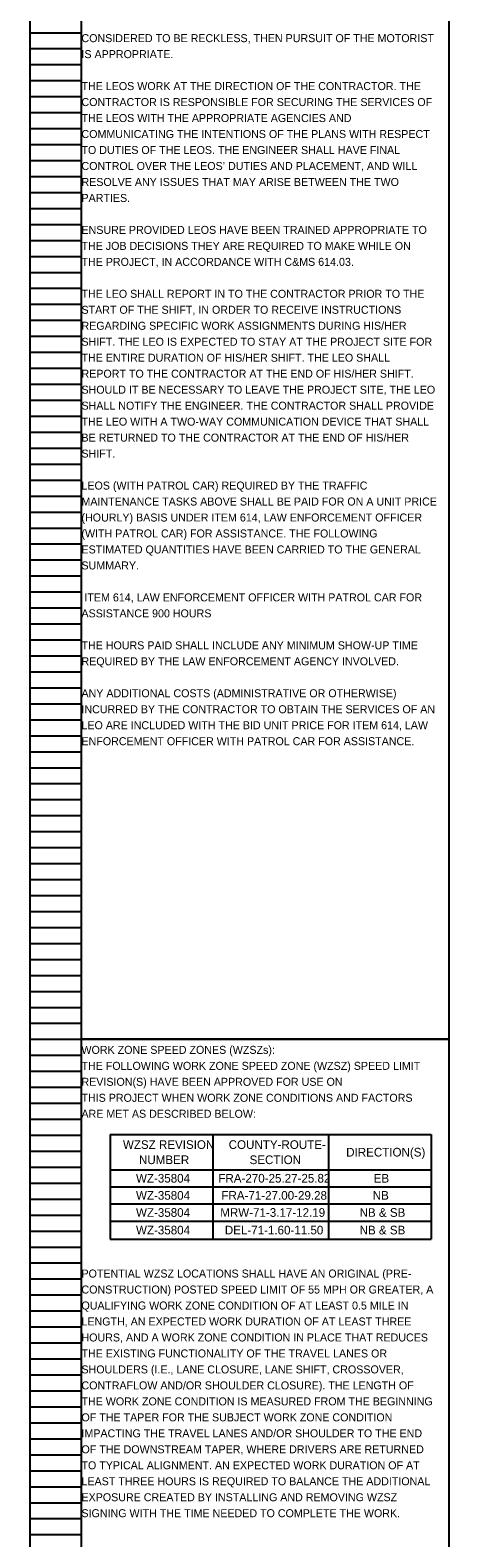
# Model space of a CAD drawing. Extents: x 16463 to 16500, y 5400 to 5823.
# Drawn here: x 16463.05 to 16470.39, y 5532.5 to 5558.92 of the extents above; entities that cross this region are included whole.
import ezdxf

# ---------------------------------------------------------------- set-up
doc = ezdxf.new("R2010")
doc.units = 0
for name, color, linetype in [('Default', 7, 'Continuous'), ('SC_Scratch1', 7, 'Continuous'), ('SH_Data', 7, 'Continuous'), ('SH_Text', 7, 'Continuous')]:
    doc.layers.add(name, color=color, linetype=linetype)

msp = doc.modelspace()

# ---------------------------------------------------------------- linework, layer by layer
at = {"layer": 'Default'}
for p, q in [((16464.454, 5539.562), (16470.079, 5539.562)), ((16464.454, 5539.562), (16464.454, 5537.732)), ((16466.254, 5539.562), (16466.254, 5537.732)), ((16468.279, 5539.562), (16468.279, 5537.732)), ((16470.079, 5539.562), (16470.079, 5537.732)), ((16464.454, 5538.947), (16470.079, 5538.947)), ((16464.454, 5538.647), (16470.079, 5538.647)), ((16464.454, 5538.347), (16470.079, 5538.347)), ((16464.454, 5538.047), (16470.079, 5538.047)), ((16464.454, 5537.732), (16470.079, 5537.732))]:
    msp.add_line(p, q, dxfattribs=at)
at = {"layer": 'SC_Scratch1'}
for points in [[(16463.949, 5561.392), (16470.389, 5561.392), (16470.389, 5541.232), (16463.949, 5541.232)], [(16463.949, 5541.232), (16470.389, 5541.232), (16470.389, 5521.072), (16463.949, 5521.072)]]:
    msp.add_lwpolyline(points, close=True, dxfattribs=at)
at = {"layer": 'SH_Data'}
for p, q in [((16463.049, 5541.232), (16463.049, 5561.392)), ((16463.949, 5541.232), (16463.949, 5561.392)), ((16463.049, 5558.872), (16463.949, 5558.872)), ((16463.049, 5558.592), (16463.949, 5558.592)), ((16463.049, 5558.312), (16463.949, 5558.312)), ((16463.049, 5558.032), (16463.949, 5558.032)), ((16463.049, 5557.752), (16463.949, 5557.752)), ((16463.049, 5557.472), (16463.949, 5557.472)), ((16463.049, 5557.192), (16463.949, 5557.192)), ((16463.049, 5556.912), (16463.949, 5556.912)), ((16463.049, 5556.632), (16463.949, 5556.632)), ((16463.049, 5556.352), (16463.949, 5556.352)), ((16463.049, 5556.072), (16463.949, 5556.072)), ((16463.049, 5555.792), (16463.949, 5555.792)), ((16463.049, 5555.512), (16463.949, 5555.512)), ((16463.049, 5555.232), (16463.949, 5555.232)), ((16463.049, 5554.952), (16463.949, 5554.952)), ((16463.049, 5554.672), (16463.949, 5554.672)), ((16463.049, 5554.392), (16463.949, 5554.392)), ((16463.049, 5554.112), (16463.949, 5554.112)), ((16463.049, 5553.832), (16463.949, 5553.832)), ((16463.049, 5553.552), (16463.949, 5553.552)), ((16463.049, 5553.272), (16463.949, 5553.272)), ((16463.049, 5552.992), (16463.949, 5552.992)), ((16463.049, 5552.712), (16463.949, 5552.712)), ((16463.049, 5552.432), (16463.949, 5552.432)), ((16463.049, 5552.152), (16463.949, 5552.152)), ((16463.049, 5551.872), (16463.949, 5551.872)), ((16463.049, 5551.592), (16463.949, 5551.592)), ((16463.049, 5551.312), (16463.949, 5551.312)), ((16463.049, 5551.032), (16463.949, 5551.032)), ((16463.049, 5550.752), (16463.949, 5550.752)), ((16463.049, 5550.472), (16463.949, 5550.472)), ((16463.049, 5550.192), (16463.949, 5550.192)), ((16463.049, 5549.912), (16463.949, 5549.912)), ((16463.049, 5549.632), (16463.949, 5549.632)), ((16463.049, 5549.352), (16463.949, 5549.352)), ((16463.049, 5549.072), (16463.949, 5549.072)), ((16463.049, 5548.792), (16463.949, 5548.792)), ((16463.049, 5548.512), (16463.949, 5548.512)), ((16463.049, 5548.232), (16463.949, 5548.232)), ((16463.049, 5547.952), (16463.949, 5547.952)), ((16463.049, 5547.672), (16463.949, 5547.672)), ((16463.049, 5547.392), (16463.949, 5547.392)), ((16463.049, 5547.112), (16463.949, 5547.112)), ((16463.049, 5546.832), (16463.949, 5546.832)), ((16463.049, 5546.552), (16463.949, 5546.552)), ((16463.049, 5546.272), (16463.949, 5546.272)), ((16463.049, 5545.992), (16463.949, 5545.992)), ((16463.049, 5545.712), (16463.949, 5545.712)), ((16463.049, 5545.432), (16463.949, 5545.432)), ((16463.049, 5545.152), (16463.949, 5545.152)), ((16463.049, 5544.872), (16463.949, 5544.872)), ((16463.049, 5544.592), (16463.949, 5544.592)), ((16463.049, 5544.312), (16463.949, 5544.312)), ((16463.049, 5544.032), (16463.949, 5544.032)), ((16463.049, 5543.752), (16463.949, 5543.752)), ((16463.049, 5543.472), (16463.949, 5543.472)), ((16463.049, 5543.192), (16463.949, 5543.192)), ((16463.049, 5542.912), (16463.949, 5542.912)), ((16463.049, 5542.632), (16463.949, 5542.632)), ((16463.049, 5542.352), (16463.949, 5542.352)), ((16463.049, 5542.072), (16463.949, 5542.072)), ((16463.049, 5541.792), (16463.949, 5541.792)), ((16463.049, 5541.512), (16463.949, 5541.512)), ((16463.049, 5521.072), (16463.049, 5541.232)), ((16463.049, 5541.232), (16463.949, 5541.232)), ((16463.049, 5541.232), (16463.949, 5541.232)), ((16463.949, 5521.072), (16463.949, 5541.232)), ((16463.049, 5540.952), (16463.949, 5540.952)), ((16463.049, 5540.672), (16463.949, 5540.672)), ((16463.049, 5540.392), (16463.949, 5540.392)), ((16463.049, 5540.112), (16463.949, 5540.112)), ((16463.049, 5539.832), (16463.949, 5539.832)), ((16463.049, 5539.552), (16463.949, 5539.552)), ((16463.049, 5539.272), (16463.949, 5539.272)), ((16463.049, 5538.992), (16463.949, 5538.992)), ((16463.049, 5538.712), (16463.949, 5538.712)), ((16463.049, 5538.432), (16463.949, 5538.432)), ((16463.049, 5538.152), (16463.949, 5538.152)), ((16463.049, 5537.872), (16463.949, 5537.872)), ((16463.049, 5537.592), (16463.949, 5537.592)), ((16463.049, 5537.312), (16463.949, 5537.312)), ((16463.049, 5537.032), (16463.949, 5537.032)), ((16463.049, 5536.752), (16463.949, 5536.752)), ((16463.049, 5536.472), (16463.949, 5536.472)), ((16463.049, 5536.192), (16463.949, 5536.192)), ((16463.049, 5535.912), (16463.949, 5535.912)), ((16463.049, 5535.632), (16463.949, 5535.632)), ((16463.049, 5535.352), (16463.949, 5535.352)), ((16463.049, 5535.072), (16463.949, 5535.072)), ((16463.049, 5534.792), (16463.949, 5534.792)), ((16463.049, 5534.512), (16463.949, 5534.512)), ((16463.049, 5534.232), (16463.949, 5534.232)), ((16463.049, 5533.952), (16463.949, 5533.952)), ((16463.049, 5533.672), (16463.949, 5533.672)), ((16463.049, 5533.392), (16463.949, 5533.392)), ((16463.049, 5533.112), (16463.949, 5533.112)), ((16463.049, 5532.832), (16463.949, 5532.832)), ((16463.049, 5532.552), (16463.949, 5532.552))]:
    msp.add_line(p, q, dxfattribs=at)

# ---------------------------------------------------------------- texts
at = {"layer": 'Default'}
for s, p in [('WZSZ REVISION ', (16464.676, 5539.311)), ('COUNTY-ROUTE-', (16466.53, 5539.311)), ('NUMBER', (16464.958, 5539.045)), ('SECTION', (16466.896, 5539.045)), ('DIRECTION(S)', (16468.59, 5539.178)), ('WZ-35804', (16464.905, 5538.721)), ('FRA-270-25.27-25.82', (16466.349, 5538.721)), ('EB', (16469.072, 5538.721)), ('WZ-35804', (16464.905, 5538.421)), ('FRA-71-27.00-29.28', (16466.402, 5538.421)), ('NB', (16469.055, 5538.421)), ('WZ-35804', (16464.905, 5538.121)), ('MRW-71-3.17-12.19', (16466.382, 5538.121)), ('NB & SB', (16468.825, 5538.121)), ('WZ-35804', (16464.905, 5537.813)), ('DEL-71-1.60-11.50', (16466.462, 5537.813)), ('NB & SB', (16468.825, 5537.813))]:
    msp.add_text(s, height=0.1518, dxfattribs=at).set_placement(p)
at = {"layer": 'SH_Text'}
for s, p in [('CONSIDERED TO BE RECKLESS, THEN PURSUIT OF THE MOTORIST ', (16463.949, 5558.706)), ('IS APPROPRIATE. ', (16463.949, 5558.426)), ('THE LEOS WORK AT THE DIRECTION OF THE CONTRACTOR. THE ', (16463.949, 5557.866)), ('CONTRACTOR IS RESPONSIBLE FOR SECURING THE SERVICES OF ', (16463.949, 5557.586)), ('THE LEOS WITH THE APPROPRIATE AGENCIES AND ', (16463.949, 5557.306)), ('COMMUNICATING THE INTENTIONS OF THE PLANS WITH RESPECT ', (16463.949, 5557.026)), ('TO DUTIES OF THE LEOS. THE ENGINEER SHALL HAVE FINAL ', (16463.949, 5556.746)), ('CONTROL OVER THE LEOS’ DUTIES AND PLACEMENT, AND WILL ', (16463.949, 5556.466)), ('RESOLVE ANY ISSUES THAT MAY ARISE BETWEEN THE TWO ', (16463.949, 5556.186)), ('PARTIES. ', (16463.949, 5555.906)), ('ENSURE PROVIDED LEOS HAVE BEEN TRAINED APPROPRIATE TO ', (16463.949, 5555.346)), ('THE JOB DECISIONS THEY ARE REQUIRED TO MAKE WHILE ON ', (16463.949, 5555.066)), ('THE PROJECT, IN ACCORDANCE WITH C&MS 614.03. ', (16463.949, 5554.786)), ('THE LEO SHALL REPORT IN TO THE CONTRACTOR PRIOR TO THE ', (16463.949, 5554.226)), ('START OF THE SHIFT, IN ORDER TO RECEIVE INSTRUCTIONS ', (16463.949, 5553.946)), ('REGARDING SPECIFIC WORK ASSIGNMENTS DURING HIS/HER ', (16463.949, 5553.666)), ('SHIFT. THE LEO IS EXPECTED TO STAY AT THE PROJECT SITE FOR ', (16463.949, 5553.386)), ('THE ENTIRE DURATION OF HIS/HER SHIFT. THE LEO SHALL ', (16463.949, 5553.106)), ('REPORT TO THE CONTRACTOR AT THE END OF HIS/HER SHIFT. ', (16463.949, 5552.826)), ('SHOULD IT BE NECESSARY TO LEAVE THE PROJECT SITE, THE LEO ', (16463.949, 5552.546)), ('SHALL NOTIFY THE ENGINEER. THE CONTRACTOR SHALL PROVIDE ', (16463.949, 5552.266)), ('THE LEO WITH A TWO-WAY COMMUNICATION DEVICE THAT SHALL ', (16463.949, 5551.986)), ('BE RETURNED TO THE CONTRACTOR AT THE END OF HIS/HER ', (16463.949, 5551.706)), ('SHIFT.', (16463.949, 5551.426)), ('LEOS (WITH PATROL CAR) REQUIRED BY THE TRAFFIC ', (16463.949, 5550.866)), ('MAINTENANCE TASKS ABOVE SHALL BE PAID FOR ON A UNIT PRICE ', (16463.949, 5550.586)), ('(HOURLY) BASIS UNDER ITEM 614, LAW ENFORCEMENT OFFICER ', (16463.949, 5550.306)), ('(WITH PATROL CAR) FOR ASSISTANCE. THE FOLLOWING ', (16463.949, 5550.026)), ('ESTIMATED QUANTITIES HAVE BEEN CARRIED TO THE GENERAL ', (16463.949, 5549.746)), ('SUMMARY.', (16463.949, 5549.466)), (' ITEM 614, LAW ENFORCEMENT OFFICER WITH PATROL CAR FOR ', (16463.949, 5548.906)), ('ASSISTANCE 900 HOURS ', (16463.949, 5548.626)), ('THE HOURS PAID SHALL INCLUDE ANY MINIMUM SHOW-UP TIME ', (16463.949, 5548.066)), ('REQUIRED BY THE LAW ENFORCEMENT AGENCY INVOLVED. ', (16463.949, 5547.786)), ('ANY ADDITIONAL COSTS (ADMINISTRATIVE OR OTHERWISE) ', (16463.949, 5547.226)), ('INCURRED BY THE CONTRACTOR TO OBTAIN THE SERVICES OF AN ', (16463.949, 5546.946)), ('LEO ARE INCLUDED WITH THE BID UNIT PRICE FOR ITEM 614, LAW ', (16463.949, 5546.666)), ('ENFORCEMENT OFFICER WITH PATROL CAR FOR ASSISTANCE.', (16463.949, 5546.386)), ('WORK ZONE SPEED ZONES (WZSZs):', (16463.949, 5540.977)), ('THE FOLLOWING WORK ZONE SPEED ZONE (WZSZ) SPEED LIMIT ', (16463.949, 5540.697)), ('REVISION(S) HAVE BEEN APPROVED FOR USE ON', (16463.949, 5540.417)), ('THIS PROJECT WHEN WORK ZONE CONDITIONS AND FACTORS ', (16463.949, 5540.137)), ('ARE MET AS DESCRIBED BELOW: ', (16463.949, 5539.857)), ('POTENTIAL WZSZ LOCATIONS SHALL HAVE AN ORIGINAL (PRE-', (16463.949, 5537.057)), ('CONSTRUCTION) POSTED SPEED LIMIT OF 55 MPH OR GREATER, A ', (16463.949, 5536.777)), ('QUALIFYING WORK ZONE CONDITION OF AT LEAST 0.5 MILE IN ', (16463.949, 5536.497)), ('LENGTH, AN EXPECTED WORK DURATION OF AT LEAST THREE ', (16463.949, 5536.217)), ('HOURS, AND A WORK ZONE CONDITION IN PLACE THAT REDUCES ', (16463.949, 5535.937)), ('THE EXISTING FUNCTIONALITY OF THE TRAVEL LANES OR ', (16463.949, 5535.657)), ('SHOULDERS (I.E., LANE CLOSURE, LANE SHIFT, CROSSOVER, ', (16463.949, 5535.377)), ('CONTRAFLOW AND/OR SHOULDER CLOSURE). THE LENGTH OF ', (16463.949, 5535.097)), ('THE WORK ZONE CONDITION IS MEASURED FROM THE BEGINNING ', (16463.949, 5534.817)), ('OF THE TAPER FOR THE SUBJECT WORK ZONE CONDITION ', (16463.949, 5534.537)), ('IMPACTING THE TRAVEL LANES AND/OR SHOULDER TO THE END ', (16463.949, 5534.257)), ('OF THE DOWNSTREAM TAPER, WHERE DRIVERS ARE RETURNED ', (16463.949, 5533.977)), ('TO TYPICAL ALIGNMENT. AN EXPECTED WORK DURATION OF AT ', (16463.949, 5533.697)), ('LEAST THREE HOURS IS REQUIRED TO BALANCE THE ADDITIONAL ', (16463.949, 5533.417)), ('EXPOSURE CREATED BY INSTALLING AND REMOVING WZSZ ', (16463.949, 5533.137)), ('SIGNING WITH THE TIME NEEDED TO COMPLETE THE WORK. ', (16463.949, 5532.857))]:
    msp.add_text(s, height=0.14, dxfattribs=at).set_placement(p)

doc.saveas('drawing.dxf')
